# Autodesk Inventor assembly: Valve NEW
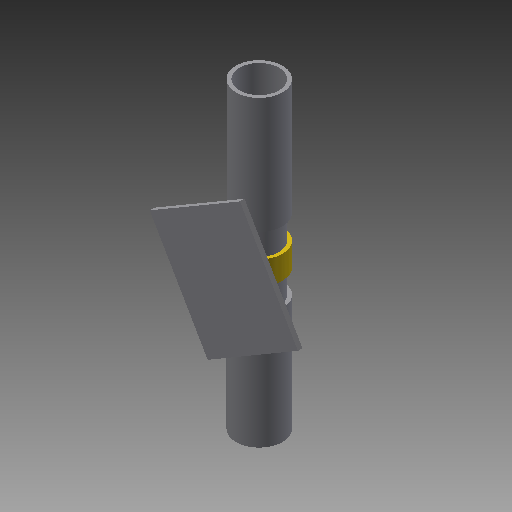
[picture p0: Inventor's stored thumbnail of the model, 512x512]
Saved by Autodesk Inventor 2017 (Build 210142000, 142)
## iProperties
Created: 2020-03
Part Number: Valve NEW
Description: STEP AP203
Document SubType Name: Assembly
Designer: user
Sending System: SolidWorks 2018
Preprocessor: SwSTEP 2.0
Title: Assem1.STEP
Revision Number: ANY
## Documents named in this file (8)
- C:\Users\user\Documents\Inventor\Home Ventilator CPAP\Valve NEW.iam
- C:\Users\user\Documents\Inventor\Home Ventilator CPAP\ball.ipt
- C:\Users\user\Documents\Inventor\Home Ventilator CPAP\bracket.ipt
- C:\Users\user\Documents\Inventor\Home Ventilator CPAP\rubber seal.ipt
- C:\Users\user\Documents\Inventor\Home Ventilator CPAP\Syringe.ipt
- C:\Users\user\Documents\Inventor\Home Ventilator CPAP\Tube.ipt
- C:\Users\user\Documents\Inventor\Home Ventilator CPAP\interrupt.ipt
- C:\Users\user\Documents\Inventor\Home Ventilator CPAP\Ring valve.ipt
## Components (8 placed, 8 different names)
1. ball_1
2. bracket_2
3. rubber seal_3
4. Syringe_4 — Mate:1
5. Tube_5 — Mate:2
6. Tube_6
7. interrupt_7
8. Ring valve:1 — Mate:1, Mate:2
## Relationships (2: Mate 2)
- Mate:1: Syringe_4 ↔ Ring valve:1
- Mate:2: Tube_5 ↔ Ring valve:1
